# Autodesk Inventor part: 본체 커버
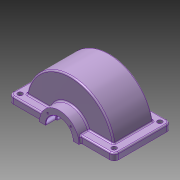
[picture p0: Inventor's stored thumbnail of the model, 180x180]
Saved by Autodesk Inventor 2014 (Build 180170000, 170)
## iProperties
Created: 2023-06
Part Number: 본체 커버
Material: 알루미늄 6061
Document SubType Name: Modeling
Designer: mdu-01
Density: 2.71 g/cm^3
Mass: 2296.01 g
Surface Area: 1364.02 cm^2
Volume: 847.238 cm^3
Appearance: 알루미늄 - 평지(1)
Author: mdu-01
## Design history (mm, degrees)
sketch "스케치1"
  geometry: L1 (0, 70)-(0, -70); L2 (0, 70)-(45, 70); L3 (45, 70)-(45, 45); L4 (45, 45)-(100, 45); L5 (0, 0)-(100, 0); L6 (0, -70)-(45, -70); L7 (45, -70)-(45, -45); L8 (45, -45)-(100, -45); L9 (100, 45)-(100, -45); 1 further point
  constraints: 18 end point, 3 perpendicular, 3 symmetric about line, 2 midpoint, 2 parallel, 1 coincident, 1 vertical
  dimensions: "d0" = 140 distance of L1.start L1.end; "d1" = 90 diameter of L3 L1; "d2" = 90 distance between parallel lines of L8 L4; "d3" = 200 diameter of L9 L1
revolve "회전1" sketch "스케치1" stored, may be unused: angle "d4" = 180 deg
sketch "스케치2"
  geometry: L1 (-10, -110)-(210, -110); L2 (220, -100)-(220, 10); L3 (210, 20)-(-10, 20); L4 (-20, 10)-(-20, -100); L5 (-20, -110)-(220, 20); L6 (220, -110)-(-20, 20); A1 r 10 centre (-10, 10) between (-10, 20) and (-20, 10); A2 r 10 centre (210, 10) between (220, 10) and (210, 20); A3 r 10 centre (210, -100) between (210, -110) and (220, -100); A4 r 10 centre (-10, -100) between (-20, -100) and (-10, -110); 1 further point
  constraints: 12 end point, 8 point on circle, 8 point on line, 8 tangent, 4 centre point, 3 equal radius, 2 midpoint, 2 parallel, 1 horizontal, 1 perpendicular
  dimensions: "d5" = 240 distance of L6.end L5.end; "d6" = 130 distance of L5.end L6.start; "d7" = 10 radius of A1
extrude "돌출1" join sketch "스케치2" distance "d8" = 15; taper "d9" = 0 deg
sketch "스케치3"
  geometry: L1 (0, 70)-(45, 70) reference; L2 (0, -70)-(45, -70) reference; L3 (0, 70)-(0, -70); L4 (31, 70)-(31, 48); L5 (30, 47)-(27.5, 47); L6 (27.5, 47)-(27.5, 32); L7 (27.5, 32)-(87, 32); L8 (0, 0)-(92.097, 0); L9 (31, -70)-(31, -48); L10 (30, -47)-(27.5, -47); L11 (27.5, -47)-(27.5, -32); L12 (27.5, -32)-(87, -32); L13 (87, 32)-(87, -32); L14 (0, 70)-(31, 70); L15 (0, -70)-(31, -70); A1 r 1 centre (30, 48) between (30, 47) and (31, 48); A2 r 1 centre (30, -48) between (31, -48) and (30, -47); 2 further points
  constraints: 26 end point, 5 point on line, 5 symmetric about line, 4 parallel, 4 point on circle, 4 tangent, 3 perpendicular, 2 centre point, 2 collinear, 1 equal radius
  dimensions: "d10" = 1 radius of A1; "d11" = 62 diameter of L4 L3; "d12" = 23 distance between parallel lines of L1 L5; "d13" = 64 distance between parallel lines of L12 L7; "d14" = 55 diameter of L6 L3; "d15" = 87 distance between parallel lines of L13 L3
revolve "회전2" sketch "스케치3" stored, may be unused: angle "d16" = 180 deg
fillet "모깎기1" dims "d17" = 3
fillet "모깎기2" dims "d18" = 3
sketch "스케치4"
  geometry: L1 (-7, -7)-(207, -7); L2 (207, -7)-(207, 97); L3 (207, 97)-(-7, 97); L4 (-7, 97)-(-7, -7); L5 (-7, -7)-(207, 97); L6 (207, -7)-(-7, 97); 1 further point
  constraints: 12 end point, 2 midpoint, 2 parallel, 1 horizontal, 1 perpendicular
  dimensions: "d19" = 214 distance of L3.end L2.end; "d20" = 104 distance of L2.end L1.end
hole "구멍1" sketch "스케치4" at (207, -7), (-7, -7), (207, 97), (-7, 97) diameter "d21" = 6.6; stored, may be unused: countersink angle "d25" = 90 deg, drill point angle "d27" = 118 deg; dims "d22" = 6, "d23" = 11, "d24" = 6.8, "d26" = 8
sketch "스케치5"
  geometry: L1 (-26.163, 26.163)-(26.163, 26.163); L2 (26.163, 26.163)-(26.163, -26.163); L3 (26.163, -26.163)-(-26.163, -26.163); L4 (-26.163, -26.163)-(-26.163, 26.163); A1 r 37 centre (0, 0) between (-26.163, 26.163) and (26.163, -26.163); 1 further point
  constraints: 8 end point, 3 point on circle, 2 parallel, 2 perpendicular, 1 centre point, 1 coincident, 1 horizontal
  dimensions: "d28" = 74 diameter of A1
hole "구멍2" sketch "스케치5" at (-26.163, 26.163), (26.163, 26.163) diameter "d29" = 4.134; stored, may be unused: countersink angle "d33" = 90 deg, drill point angle "d35" = 118 deg; dims "d30" = 10, "d31" = 11, "d32" = 6.8, "d34" = 12
chamfer "모따기1" distance "d36" = 1; stored, may be unused: second distance "d37" = 2, angle "d38" = 45 deg
node "솔리드1"
mirror "대칭1"
